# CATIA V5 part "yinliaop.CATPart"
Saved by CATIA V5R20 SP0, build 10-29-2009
Part number: 饮料瓶
Material "无"
Bounding box of the stored display mesh (mm): x -25 to 26, y -25 to 25, z 0 to 110
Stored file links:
  C:\Users\GBH\Desktop\180511415郭柏宏\yinliaop.CATPart
  D:\CATIAR20\win_b64\startup\materials\Catalog.CATMaterial
  D:\CATIAR20\win_b64\startup\materials\brushed_metal2.jpg
  D:\CATIAR20\win_b64\startup\materials\brushed_metal1.jpg
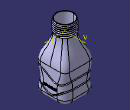
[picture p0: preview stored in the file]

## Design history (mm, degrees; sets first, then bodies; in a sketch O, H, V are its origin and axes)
Set1
  Sketch1 on xy-plane, origin (0, 0, 0), H (1, 0, 0), V (0, 1, 0)
    line L1 (25, 25) -> (25, -25)
    line L2 (25, -25) -> (-25, -25)
    line L3 (-25, -25) -> (-25, 25)
    line L4 (-25, 25) -> (25, 25)
    length L1 = 50
    length L4 = 50
    vertical: L1 V, L3 V
    horizontal: L2 H, L4 H
    equidistance: L1 L3 O, L2 L4 O
  Sketch2 on face of Pad1 from Sketch1.L1, origin (25, 0, 0), H (0, 1, 0), V (0, 0, 1)
    spline S1 through (-40, 10) (-20, 20) (0, 10) (20, 20) (40, 20)
    point P1 (0, 10)
    coincidence: P1 V
  Extrude1: Element1 Sketch2, Lim1 54, Lim2 54
  MultiSel1: CommonCtxFeats ({extract ExtractElem face of Pad1 from Sketch1.L3}; {extract ExtractElem face of Fillet1}; {extract ExtractElem face of Pad1 from Sketch1.L2}; {extract ExtractElem face of Fillet1}; {extract ExtractElem face of Pad1 from Sketch1.L1}; {extract ExtractElem face of Fillet1}; {extract ExtractElem face of Pad1 from Sketch1.L4}; {extract ExtractElem face of Fillet1})
  Sketch3 on face of Pad1 from Sketch1.L1, origin (25, 0, 0), H (0, 1, 0), V (0, 0, 1)
    spline S1 through (-50, 30) (-10, 40) (10, 30) (30, 40)
  Extrude2: Element1 Sketch3, Lim1 54, Lim2 54
  MultiSel2: CommonCtxFeats ({extract ExtractElem face of Fillet1}; {extract ExtractElem face of Pad1 from Sketch1.L3}; {extract ExtractElem face of Fillet1}; {extract ExtractElem face of Pad1 from Sketch1.L4}; {extract ExtractElem face of Fillet1}; {extract ExtractElem face of Pad1 from Sketch1.L1}; {extract ExtractElem face of Fillet1}; {extract ExtractElem face of Pad1 from Sketch1.L2})
  Join1: Elements ({intersect ToIntersect1 {extract ExtractElem face of Pad1 from Sketch1.L3}, ToIntersect2 Extrude1}; {intersect ToIntersect1 {extract ExtractElem face of Fillet1}, ToIntersect2 Extrude1}; {intersect ToIntersect1 {extract ExtractElem face of Pad1 from Sketch1.L2}, ToIntersect2 Extrude1}; {intersect ToIntersect1 {extract ExtractElem face of Fillet1}, ToIntersect2 Extrude1}; {intersect ToIntersect1 {extract ExtractElem face of Pad1 from Sketch1.L1}, ToIntersect2 Extrude1}; {intersect ToIntersect1 {extract ExtractElem face of Fillet1}, ToIntersect2 Extrude1}; {intersect ToIntersect1 {extract ExtractElem face of Pad1 from Sketch1.L4}, ToIntersect2 Extrude1}; {intersect ToIntersect1 {extract ExtractElem face of Fillet1}, ToIntersect2 Extrude1})
  Join2: Elements ({intersect ToIntersect1 {extract ExtractElem face of Fillet1}, ToIntersect2 Extrude2}; {intersect ToIntersect1 {extract ExtractElem face of Pad1 from Sketch1.L3}, ToIntersect2 Extrude2}; {intersect ToIntersect1 {extract ExtractElem face of Fillet1}, ToIntersect2 Extrude2}; {intersect ToIntersect1 {extract ExtractElem face of Pad1 from Sketch1.L4}, ToIntersect2 Extrude2}; {intersect ToIntersect1 {extract ExtractElem face of Fillet1}, ToIntersect2 Extrude2}; {intersect ToIntersect1 {extract ExtractElem face of Pad1 from Sketch1.L1}, ToIntersect2 Extrude2}; {intersect ToIntersect1 {extract ExtractElem face of Fillet1}, ToIntersect2 Extrude2}; {intersect ToIntersect1 {extract ExtractElem face of Pad1 from Sketch1.L2}, ToIntersect2 Extrude2})
  Plane1: type Normal, Curve Join1, RefPoint vertex [face of MultiSel1 | face of MultiSel1]
  Circle1: type CtrRad, Start 0, End 180, Center vertex [face of MultiSel1 | face of MultiSel1], Support Plane1, Radius 1, FirstDirection (1, 0, 0)
Body1 (main body), material "无"
  Pad1: profile Sketch1, direction (0, 0, 1), length 50
  Fillet1: on edge [face of Pad1 from Sketch1.L1 | face of Pad1 from Sketch1.L2]; edge [face of Pad1 from Sketch1.L2 | face of Pad1 from Sketch1.L3]; edge [face of Pad1 from Sketch1.L3 | face of Pad1 from Sketch1.L4]; edge [face of Pad1 from Sketch1.L4 | face of Pad1 from Sketch1.L1]
  Fillet2: radius 8, on edge [start face of Pad1 | face of Pad1 from Sketch1.L3]
  Plane2: type Offset, RefPlane end face of Pad1, Offset 40, reversed
  Sketch4 on Plane2, origin (0, 0, 90), H (1, 0, 0), V (0, -1, 0)
    circle A1 centre (0, 0) radius 15
  Pad2: profile Sketch4, direction (0, 0, 1), length 20
  Sketch5 on end face of Pad1, origin (0, 0, 50), H (1, 0, 0), V (0, 1, 0)
    point P1 (25, 0)
    distance P1 O = 25
    coincidence: P1 H
  Sketch6 on start face of Pad2, origin (0, 0, 90), H (1, 0, 0), V (0, -1, 0)
    point P1 (15, 0)
    distance P1 O = 15
    coincidence: P1 H
  Loft1: solid, Sections ({boundary Boundary {extract ExtractElem end face of Pad1}}; {boundary Boundary {extract ExtractElem start face of Pad2}}), StartFace end face of Pad1, EndFace start face of Pad2
  Slot1: profile Circle1, centre curve Join1
  Plane3: type Normal, Curve Join2, RefPoint vertex [face of MultiSel2 | face of MultiSel2]
  Circle2: type CtrRad, Start 0, End 180, Center vertex [face of MultiSel2 | face of MultiSel2], Support Plane3, Radius 1, FirstDirection (0, -1, 0)
  Slot2: profile Circle2, centre curve Join2
  Shell1: IntOffset 1, Face end face of Pad2, ExtOffset 0
  Plane4: type Offset, RefPlane xy-plane, Offset 91
  Sketch7 on Plane4, origin (0, 0, 91), H (1, 0, 0), V (0, 1, 0)
    point P1 (15, 0)
    distance P1 O = 15
    coincidence: P1 H
  Helix1: Direction Z axis, RefPoint Sketch7, Pitch 3, Height 16, TaperAngle 0
  Point1: type OnCurve, Support Helix1, RefPoint vertex of Helix1, Length -5
  Line1: type PtDir, RefPoint vertex of Helix1, Direction (0, 1, 0), Start 0, End -10
  Connect1: Curve1 Line1, Point1 vertex of Line1, Tension1 1, Curve2 Helix1, Point2 Point1, Tension2 1
  Point2: type OnCurve, Support Connect1, RefPoint Sketch7, Length -5
  Line2: type PtDir, RefPoint Sketch7, Direction (1, 0, 0), Start 0, End -10
  Connect2: Curve1 Line2, Point1 vertex of Line2, Tension1 1, Curve2 Connect1, Point2 Point2, Tension2 1
  Plane5: type Normal, Curve Connect2, RefPoint vertex of Connect1
  Circle3: type CtrRad, Start 0, End 180, Center vertex of Connect1, Support Plane5, Radius 1, FirstDirection (1, 0, 0)
  Rib1: profile Circle3, centre curve Connect2
  Sketch8 on {extract ExtractElem start face of Pad2}, origin (0, 0, 90), H (1, 0, 0), V (0, 1, 0)
  Body2
    Sketch9 on Plane4, origin (0, 0, 91), H (1, 0, 0), V (0, 1, 0)
      circle A1 centre (0, 0) radius 14
      radius A1 = 14
    Pad3: profile Sketch9, direction (0, 0, 1), length 20, mirrored extent
  Remove1: tool Body2
Body3
  Sketch10 on face of Pad1 from Sketch1.L1, origin (25, 0, 0), H (0, 1, 0), V (0, 0, 1)
    polyline C1
    polyline C2
    polyline C3
    polyline C4
    polyline C5
    polyline C6
    polyline C7
    polyline C8
    polyline C9
    polyline C10
    polyline C11
  Pad4: profile Sketch10, direction (1, 0, 0), length 1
